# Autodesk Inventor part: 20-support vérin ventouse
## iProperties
Created: 2011-02
Part Number: 20-support vérin ventouse
Document SubType Name: Modeling
Designer: eric
Density: 1 g/cm^3
Author: eric
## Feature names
1. Base1
